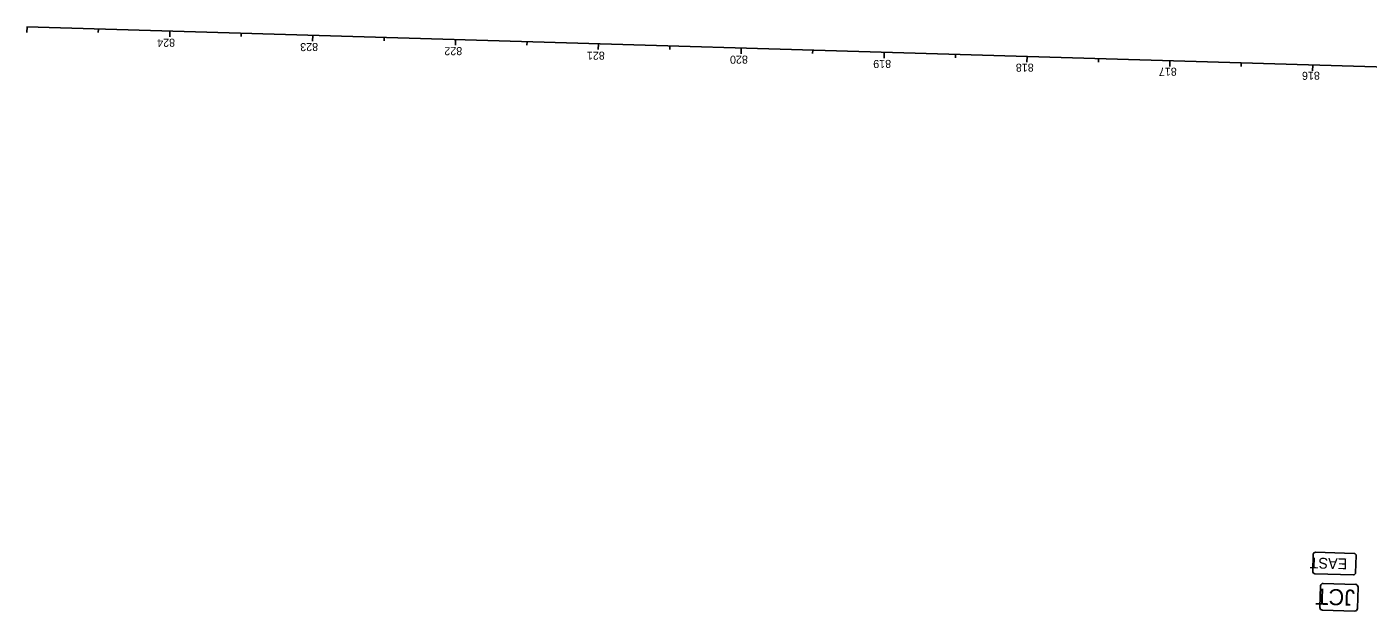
# Model space of a CAD drawing. Extents: x 1658454 to 1663955, y 480219 to 484109.
# Drawn here: x 1658454 to 1659392, y 482390 to 482799 of the extents above; entities that cross this region are included whole.
import ezdxf

# ---------------------------------------------------------------- set-up
doc = ezdxf.new("R2010")
doc.units = 0
for name, color, linetype in [('Default', 7, 'Continuous'), ('SN_X_Public', 7, 'Continuous'), ('SV_X_CL_Survey_50', 7, 'Continuous'), ('SV_X_Text', 7, 'Continuous')]:
    doc.layers.add(name, color=color, linetype=linetype)

msp = doc.modelspace()

# ---------------------------------------------------------------- linework, layer by layer
at = {"layer": 'Default'}
for p, q in [((1658453.67, 482798.87), (1658453.55, 482794.87)), ((1658503.64, 482797.39), (1658503.57, 482794.99)), ((1658553.62, 482795.9), (1658553.5, 482791.9)), ((1658603.6, 482794.42), (1658603.53, 482792.02)), ((1658653.58, 482792.94), (1658653.46, 482788.94)), ((1658703.56, 482791.45), (1658703.48, 482789.05)), ((1658753.53, 482789.97), (1658753.41, 482785.97)), ((1658803.51, 482788.48), (1658803.44, 482786.08)), ((1658853.49, 482787), (1658853.37, 482783)), ((1658903.47, 482785.52), (1658903.4, 482783.12)), ((1658953.45, 482784.03), (1658953.33, 482780.03)), ((1659003.42, 482782.55), (1659003.35, 482780.15)), ((1659053.4, 482781.06), (1659053.28, 482777.07)), ((1659103.38, 482779.58), (1659103.31, 482777.18)), ((1659153.36, 482778.1), (1659153.24, 482774.1)), ((1659203.34, 482776.61), (1659203.26, 482774.21)), ((1659253.31, 482775.13), (1659253.19, 482771.13)), ((1659303.29, 482773.64), (1659303.22, 482771.25)), ((1659353.27, 482772.16), (1659353.15, 482768.16))]:
    msp.add_line(p, q, dxfattribs=at)
at = {"layer": 'SN_X_Public'}
for p, q in [((1659353.29, 482418.15), (1659353.64, 482430.14)), ((1659355.19, 482431.6), (1659382.18, 482430.8)), ((1659383.63, 482429.25), (1659383.27, 482417.26)), ((1659381.73, 482415.8), (1659354.74, 482416.6))]:
    msp.add_line(p, q, dxfattribs=at)
for points in [[(1659358.72, 482408.01), (1659358.27, 482393.02)], [(1659383.14, 482409.16), (1659360.65, 482409.83)], [(1659384.51, 482392.24), (1659384.95, 482407.23)], [(1659360.09, 482391.09), (1659382.58, 482390.42)]]:
    msp.add_lwpolyline(points, dxfattribs=at)
for centre, radius, start, end in [((1659355.14, 482430.1), 1.5, 88.29934, 178.29934), ((1659382.13, 482429.3), 1.5, 358.29934, 88.29934), ((1659354.79, 482418.1), 1.5, 178.29934, 268.29934), ((1659381.78, 482417.3), 1.5, 268.29934, 358.29934), ((1659360.59, 482407.95), 1.88, 88.29934, 178.29934), ((1659383.08, 482407.29), 1.88, 358.29934, 88.29934), ((1659360.14, 482392.96), 1.88, 178.29934, 268.29934), ((1659382.64, 482392.29), 1.88, 268.29934, 358.29934)]:
    msp.add_arc(centre, radius, start, end, dxfattribs=at)
at = {"layer": 'SV_X_CL_Survey_50'}
msp.add_line((1663951.73, 482635.63), (1658453.66, 482798.87), dxfattribs=at)

# ---------------------------------------------------------------- texts
at = {"layer": 'SN_X_Public'}
for s, height, p in [('EAST', 7.5, (1659377.47, 482427.18)), ('JCT', 11.25, (1659382.92, 482405.42))]:
    msp.add_text(s, height=height, rotation=178.29934, dxfattribs=at).set_placement(p)
at = {"layer": 'SV_X_Text'}
for s, p in [('824', (1658557.23, 482790.58)), ('823', (1658657.31, 482787.6)), ('822', (1658758.15, 482784.72)), ('821', (1658857.87, 482781.54)), ('820', (1658958, 482778.81)), ('819', (1659058.23, 482775.79)), ('818', (1659157.99, 482773.2)), ('817', (1659258.08, 482770.33)), ('816', (1659358.21, 482767.54))]:
    msp.add_text(s, height=5.6, rotation=180.53411, dxfattribs=at).set_placement(p)

doc.saveas('drawing.dxf')
